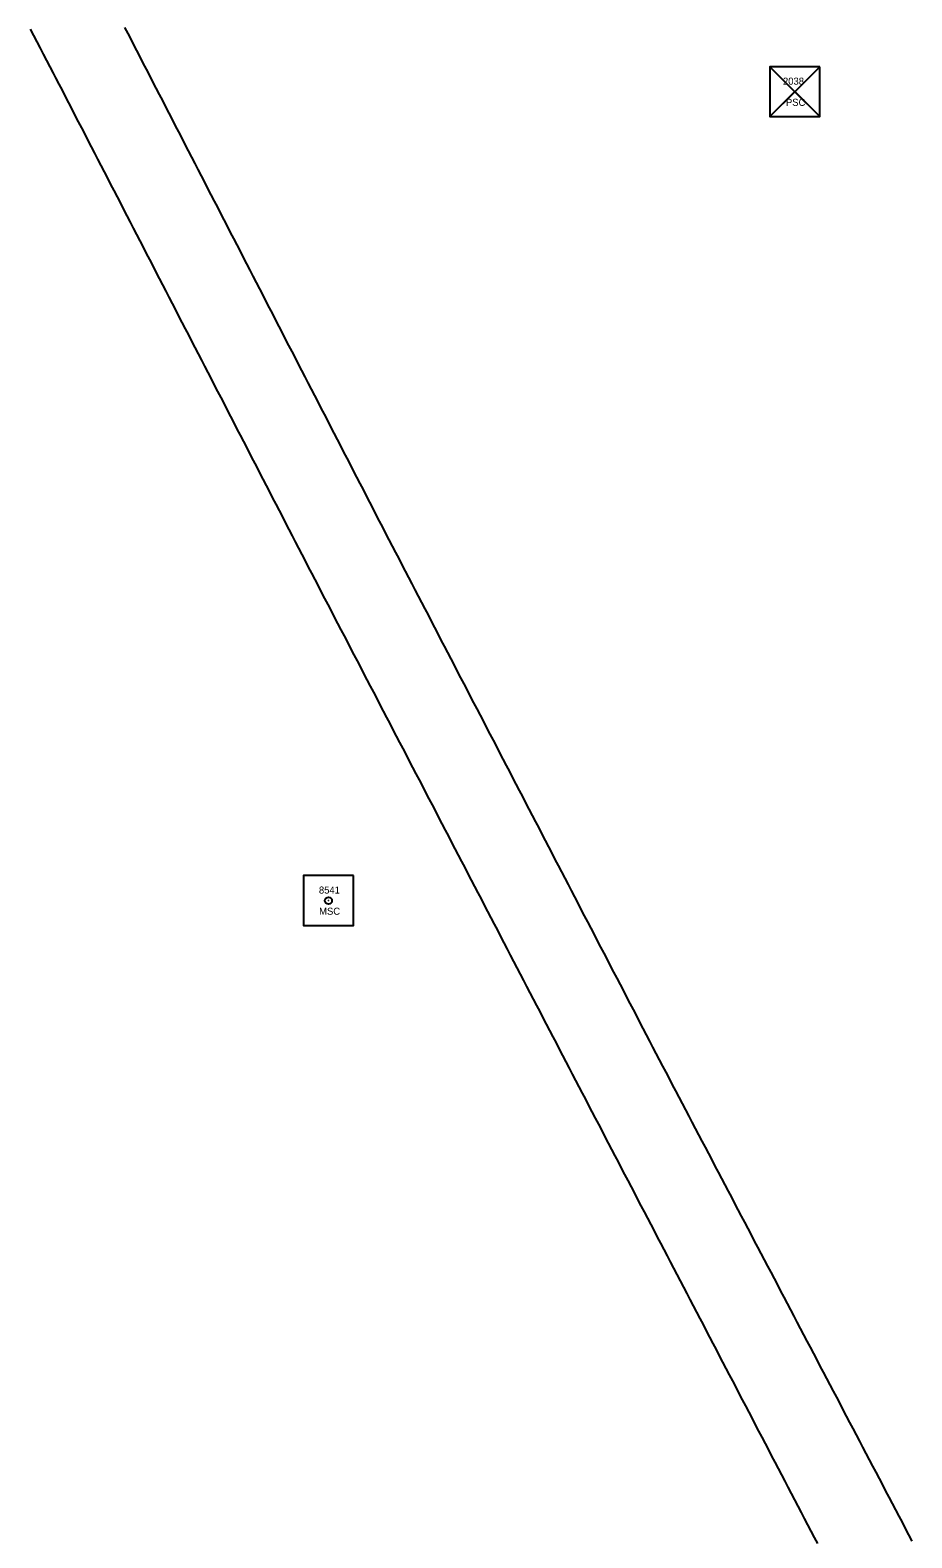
# Model space of a CAD drawing. Extents: x 205929 to 2357175, y -1785700 to 846739.
# Drawn here: x 2012224.1 to 2012349, y 825016.1 to 825229.6 of the extents above; entities that cross this region are included whole.
import ezdxf

# ---------------------------------------------------------------- set-up
doc = ezdxf.new("R2010")
doc.units = 0
for name, color, linetype in [('RD_HC_Survey', 7, 'Continuous'), ('RD_HC_txCode', 7, 'Continuous'), ('RD_Sketch1', 7, 'Continuous'), ('RD_SMD_Locator', 7, 'Continuous')]:
    doc.layers.add(name, color=color, linetype=linetype)

msp = doc.modelspace()

# ---------------------------------------------------------------- linework, layer by layer
at = {"layer": 'RD_HC_Survey'}
for p, q in [((2012328.86, 825224.42), (2012335.93, 825217.35)), ((2012335.93, 825224.42), (2012328.86, 825217.35)), ((2012335.93, 825224.42), (2012328.86, 825224.42)), ((2012328.86, 825224.42), (2012332.39, 825220.88)), ((2012332.39, 825220.88), (2012335.93, 825224.42)), ((2012332.39, 825220.88), (2012328.86, 825217.35)), ((2012335.93, 825217.35), (2012332.39, 825220.88)), ((2012328.86, 825217.35), (2012335.93, 825217.35))]:
    msp.add_line(p, q, dxfattribs=at)
for points in [[(2012335.93, 825224.42), (2012328.86, 825224.42), (2012328.86, 825217.35), (2012335.93, 825217.35)], [(2012269.87, 825109.85), (2012262.8, 825109.85), (2012262.8, 825102.78), (2012269.87, 825102.78)]]:
    msp.add_lwpolyline(points, close=True, dxfattribs=at)
msp.add_circle((2012266.34, 825106.31), 0.5, dxfattribs=at)
at = {"layer": 'RD_Sketch1'}
for points in [[(2012224.09, 825229.72), (2012224.56, 825228.84), (2012225.02, 825227.95), (2012225.49, 825227.07), (2012225.95, 825226.18), (2012226.41, 825225.29), (2012226.88, 825224.41), (2012227.34, 825223.52), (2012227.69, 825222.86), (2012228.15, 825221.97), (2012228.61, 825221.09), (2012229.07, 825220.2), (2012229.52, 825219.31), (2012229.98, 825218.42), (2012230.44, 825217.53), (2012230.9, 825216.64), (2012231.36, 825215.76), (2012231.82, 825214.87), (2012232.28, 825213.98), (2012232.74, 825213.09), (2012233.19, 825212.2), (2012233.65, 825211.31), (2012234.11, 825210.42), (2012234.57, 825209.54), (2012235.03, 825208.65), (2012235.49, 825207.76), (2012235.95, 825206.87), (2012236.41, 825205.98), (2012236.87, 825205.09), (2012237.32, 825204.2), (2012237.78, 825203.32), (2012238.24, 825202.43), (2012238.7, 825201.54), (2012239.16, 825200.65), (2012239.62, 825199.76), (2012240.08, 825198.87), (2012240.54, 825197.99), (2012240.99, 825197.1), (2012241.45, 825196.21), (2012241.91, 825195.32), (2012242.37, 825194.43), (2012242.83, 825193.54), (2012243.29, 825192.65), (2012243.75, 825191.77), (2012244.21, 825190.88), (2012244.67, 825189.99), (2012245.12, 825189.1), (2012245.58, 825188.21), (2012246.04, 825187.32), (2012246.5, 825186.43), (2012246.96, 825185.55), (2012247.42, 825184.66), (2012247.88, 825183.77), (2012248.34, 825182.88), (2012248.79, 825181.99), (2012249.25, 825181.1), (2012249.71, 825180.22), (2012250.17, 825179.33), (2012250.63, 825178.44), (2012251.09, 825177.55), (2012251.55, 825176.66), (2012252.01, 825175.77), (2012252.46, 825174.88), (2012252.92, 825174), (2012253.38, 825173.11), (2012253.84, 825172.22), (2012254.3, 825171.33), (2012254.76, 825170.44), (2012255.22, 825169.55), (2012255.68, 825168.66), (2012256.14, 825167.78), (2012256.59, 825166.89), (2012257.05, 825166), (2012257.51, 825165.11), (2012257.97, 825164.22), (2012258.43, 825163.33), (2012258.89, 825162.45), (2012259.35, 825161.56), (2012259.81, 825160.67), (2012260.26, 825159.78), (2012260.72, 825158.89), (2012261.18, 825158), (2012261.64, 825157.11), (2012262.1, 825156.23), (2012262.56, 825155.34), (2012263.02, 825154.45), (2012263.48, 825153.56), (2012263.94, 825152.67), (2012264.4, 825151.79), (2012264.86, 825150.9), (2012265.32, 825150.01), (2012265.78, 825149.12), (2012266.24, 825148.24), (2012266.71, 825147.35), (2012267.17, 825146.46), (2012267.63, 825145.58), (2012268.09, 825144.69), (2012268.55, 825143.8), (2012269.02, 825142.92), (2012269.48, 825142.03), (2012269.94, 825141.14), (2012270.4, 825140.26), (2012270.86, 825139.37), (2012271.32, 825138.48), (2012271.79, 825137.59), (2012272.25, 825136.71), (2012272.71, 825135.82), (2012273.17, 825134.93), (2012273.63, 825134.05), (2012274.09, 825133.16), (2012274.56, 825132.27), (2012275.02, 825131.39), (2012275.48, 825130.5), (2012275.94, 825129.61), (2012276.4, 825128.72), (2012276.87, 825127.84), (2012277.33, 825126.95), (2012277.79, 825126.06), (2012278.25, 825125.18), (2012278.71, 825124.29), (2012279.17, 825123.4), (2012279.64, 825122.52), (2012280.1, 825121.63), (2012280.56, 825120.74), (2012281.02, 825119.86), (2012281.48, 825118.97), (2012281.94, 825118.08), (2012282.41, 825117.19), (2012282.87, 825116.31), (2012283.33, 825115.42), (2012283.79, 825114.53), (2012284.25, 825113.65), (2012284.72, 825112.76), (2012285.18, 825111.87), (2012285.64, 825110.99), (2012286.1, 825110.1), (2012286.56, 825109.21), (2012287.02, 825108.33), (2012287.49, 825107.44), (2012287.95, 825106.55), (2012288.41, 825105.66), (2012288.87, 825104.78), (2012289.33, 825103.89), (2012289.8, 825103), (2012290.26, 825102.12), (2012290.72, 825101.23), (2012291.18, 825100.34), (2012291.64, 825099.46), (2012292.1, 825098.57), (2012292.57, 825097.68), (2012293.03, 825096.79), (2012293.49, 825095.91), (2012293.95, 825095.02), (2012294.41, 825094.13), (2012294.87, 825093.25), (2012295.34, 825092.36), (2012295.8, 825091.47), (2012296.26, 825090.59), (2012296.72, 825089.7), (2012297.18, 825088.81), (2012297.65, 825087.93), (2012298.11, 825087.04), (2012298.57, 825086.15), (2012299.03, 825085.26), (2012299.49, 825084.38), (2012299.95, 825083.49), (2012300.42, 825082.6), (2012300.88, 825081.72), (2012301.34, 825080.83), (2012301.8, 825079.94), (2012302.26, 825079.06), (2012302.73, 825078.17), (2012303.19, 825077.28), (2012303.65, 825076.4), (2012304.12, 825075.51), (2012304.58, 825074.63), (2012305.04, 825073.74), (2012305.5, 825072.85), (2012305.97, 825071.97), (2012306.43, 825071.08), (2012306.89, 825070.19), (2012307.36, 825069.31), (2012307.82, 825068.42), (2012308.28, 825067.53), (2012308.74, 825066.65), (2012309.21, 825065.76), (2012309.67, 825064.88), (2012310.13, 825063.99), (2012310.6, 825063.1), (2012311.06, 825062.22), (2012311.52, 825061.33), (2012311.98, 825060.44), (2012312.45, 825059.56), (2012312.91, 825058.67), (2012313.37, 825057.79), (2012313.84, 825056.9), (2012314.3, 825056.01), (2012314.76, 825055.13), (2012315.22, 825054.24), (2012315.69, 825053.35), (2012316.15, 825052.47), (2012316.61, 825051.58), (2012317.08, 825050.69), (2012317.54, 825049.81), (2012318, 825048.92), (2012318.46, 825048.04), (2012318.93, 825047.15), (2012319.39, 825046.26), (2012319.85, 825045.38), (2012320.32, 825044.49), (2012320.78, 825043.6), (2012321.24, 825042.72), (2012321.7, 825041.83), (2012322.17, 825040.94), (2012322.63, 825040.06), (2012323.09, 825039.17), (2012323.56, 825038.29), (2012324.02, 825037.4), (2012324.48, 825036.51), (2012324.94, 825035.63), (2012325.41, 825034.74), (2012325.87, 825033.85), (2012326.33, 825032.97), (2012326.8, 825032.08), (2012327.26, 825031.19), (2012327.72, 825030.31), (2012328.18, 825029.42), (2012328.65, 825028.54), (2012329.11, 825027.65), (2012329.57, 825026.76), (2012330.04, 825025.88), (2012330.5, 825024.99), (2012330.96, 825024.1), (2012331.42, 825023.22), (2012331.89, 825022.33), (2012332.35, 825021.45), (2012332.81, 825020.56), (2012333.28, 825019.67), (2012333.74, 825018.79), (2012334.2, 825017.9), (2012334.66, 825017.01), (2012335.13, 825016.13), (2012335.59, 825015.24)], [(2012237.44, 825229.99), (2012237.91, 825229.11), (2012238.38, 825228.22), (2012238.69, 825227.62), (2012239.15, 825226.73), (2012239.61, 825225.84), (2012240.07, 825224.95), (2012240.52, 825224.07), (2012240.98, 825223.18), (2012241.44, 825222.29), (2012241.9, 825221.4), (2012242.36, 825220.51), (2012242.82, 825219.62), (2012243.27, 825218.73), (2012243.73, 825217.84), (2012244.19, 825216.96), (2012244.65, 825216.07), (2012245.11, 825215.18), (2012245.57, 825214.29), (2012246.02, 825213.4), (2012246.48, 825212.51), (2012246.94, 825211.62), (2012247.4, 825210.73), (2012247.86, 825209.85), (2012248.32, 825208.96), (2012248.78, 825208.07), (2012249.23, 825207.18), (2012249.69, 825206.29), (2012250.15, 825205.4), (2012250.61, 825204.51), (2012251.07, 825203.63), (2012251.53, 825202.74), (2012251.98, 825201.85), (2012252.44, 825200.96), (2012252.9, 825200.07), (2012253.36, 825199.18), (2012253.82, 825198.29), (2012254.28, 825197.4), (2012254.73, 825196.52), (2012255.19, 825195.63), (2012255.65, 825194.74), (2012256.11, 825193.85), (2012256.57, 825192.96), (2012257.03, 825192.07), (2012257.48, 825191.18), (2012257.94, 825190.29), (2012258.4, 825189.41), (2012258.86, 825188.52), (2012259.32, 825187.63), (2012259.78, 825186.74), (2012260.23, 825185.85), (2012260.69, 825184.96), (2012261.15, 825184.07), (2012261.61, 825183.18), (2012262.07, 825182.3), (2012262.53, 825181.41), (2012262.99, 825180.52), (2012263.44, 825179.63), (2012263.9, 825178.74), (2012264.36, 825177.85), (2012264.82, 825176.96), (2012265.28, 825176.07), (2012265.74, 825175.19), (2012266.19, 825174.3), (2012266.65, 825173.41), (2012267.11, 825172.52), (2012267.57, 825171.63), (2012268.03, 825170.74), (2012268.49, 825169.85), (2012268.94, 825168.97), (2012269.4, 825168.08), (2012269.86, 825167.19), (2012270.32, 825166.3), (2012270.78, 825165.41), (2012271.24, 825164.52), (2012271.69, 825163.63), (2012272.15, 825162.74), (2012272.61, 825161.86), (2012273.07, 825160.97), (2012273.53, 825160.08), (2012273.99, 825159.19), (2012274.44, 825158.3), (2012274.9, 825157.41), (2012275.36, 825156.52), (2012275.83, 825155.64), (2012276.29, 825154.75), (2012276.75, 825153.86), (2012277.21, 825152.98), (2012277.67, 825152.09), (2012278.13, 825151.2), (2012278.59, 825150.31), (2012279.05, 825149.43), (2012279.52, 825148.54), (2012279.98, 825147.65), (2012280.44, 825146.77), (2012280.9, 825145.88), (2012281.36, 825144.99), (2012281.82, 825144.1), (2012282.28, 825143.22), (2012282.74, 825142.33), (2012283.2, 825141.44), (2012283.67, 825140.55), (2012284.13, 825139.67), (2012284.59, 825138.78), (2012285.05, 825137.89), (2012285.51, 825137.01), (2012285.97, 825136.12), (2012286.43, 825135.23), (2012286.89, 825134.34), (2012287.35, 825133.46), (2012287.82, 825132.57), (2012288.28, 825131.68), (2012288.74, 825130.79), (2012289.2, 825129.91), (2012289.66, 825129.02), (2012290.12, 825128.13), (2012290.58, 825127.25), (2012291.04, 825126.36), (2012291.5, 825125.47), (2012291.97, 825124.58), (2012292.43, 825123.7), (2012292.89, 825122.81), (2012293.35, 825121.92), (2012293.81, 825121.04), (2012294.27, 825120.15), (2012294.73, 825119.26), (2012295.19, 825118.37), (2012295.66, 825117.49), (2012296.12, 825116.6), (2012296.58, 825115.71), (2012297.04, 825114.82), (2012297.5, 825113.94), (2012297.96, 825113.05), (2012298.42, 825112.16), (2012298.88, 825111.28), (2012299.34, 825110.39), (2012299.81, 825109.5), (2012300.27, 825108.61), (2012300.73, 825107.73), (2012301.19, 825106.84), (2012301.65, 825105.95), (2012302.11, 825105.06), (2012302.57, 825104.18), (2012303.03, 825103.29), (2012303.49, 825102.4), (2012303.96, 825101.52), (2012304.42, 825100.63), (2012304.88, 825099.74), (2012305.34, 825098.85), (2012305.8, 825097.97), (2012306.26, 825097.08), (2012306.72, 825096.19), (2012307.18, 825095.31), (2012307.65, 825094.42), (2012308.11, 825093.53), (2012308.57, 825092.64), (2012309.03, 825091.76), (2012309.49, 825090.87), (2012309.95, 825089.98), (2012310.41, 825089.09), (2012310.87, 825088.21), (2012311.33, 825087.32), (2012311.8, 825086.43), (2012312.26, 825085.55), (2012312.72, 825084.66), (2012313.18, 825083.77), (2012313.65, 825082.89), (2012314.11, 825082), (2012314.58, 825081.12), (2012315.04, 825080.23), (2012315.51, 825079.35), (2012315.97, 825078.46), (2012316.43, 825077.57), (2012316.9, 825076.69), (2012317.36, 825075.8), (2012317.83, 825074.92), (2012318.29, 825074.03), (2012318.76, 825073.15), (2012319.22, 825072.26), (2012319.69, 825071.38), (2012320.15, 825070.49), (2012320.62, 825069.61), (2012321.08, 825068.72), (2012321.55, 825067.84), (2012322.01, 825066.95), (2012322.48, 825066.07), (2012322.94, 825065.18), (2012323.41, 825064.3), (2012323.87, 825063.41), (2012324.34, 825062.52), (2012324.8, 825061.64), (2012325.27, 825060.75), (2012325.73, 825059.87), (2012326.2, 825058.98), (2012326.66, 825058.1), (2012327.13, 825057.21), (2012327.59, 825056.33), (2012328.06, 825055.44), (2012328.52, 825054.56), (2012328.99, 825053.67), (2012329.45, 825052.79), (2012329.92, 825051.9), (2012330.38, 825051.02), (2012330.84, 825050.13), (2012331.31, 825049.24), (2012331.77, 825048.36), (2012332.24, 825047.47), (2012332.7, 825046.59), (2012333.17, 825045.7), (2012333.63, 825044.82), (2012334.1, 825043.93), (2012334.56, 825043.05), (2012335.03, 825042.16), (2012335.49, 825041.28), (2012335.96, 825040.39), (2012336.42, 825039.51), (2012336.89, 825038.62), (2012337.35, 825037.74), (2012337.82, 825036.85), (2012338.28, 825035.97), (2012338.75, 825035.08), (2012339.21, 825034.19), (2012339.68, 825033.31), (2012340.14, 825032.42), (2012340.61, 825031.54), (2012341.07, 825030.65), (2012341.54, 825029.77), (2012342, 825028.88), (2012342.47, 825028), (2012342.93, 825027.11), (2012343.4, 825026.23), (2012343.86, 825025.34), (2012344.32, 825024.46), (2012344.79, 825023.57), (2012345.25, 825022.69), (2012345.72, 825021.8), (2012346.18, 825020.91), (2012346.65, 825020.03), (2012347.11, 825019.14), (2012347.58, 825018.26), (2012348.04, 825017.37), (2012348.51, 825016.49), (2012348.97, 825015.6)]]:
    msp.add_lwpolyline(points, dxfattribs=at)
at = {"layer": 'RD_SMD_Locator'}
for centre in [(2012332.39, 825220.88), (2012266.34, 825106.31)]:
    msp.add_circle(centre, 0.001, dxfattribs=at)

# ---------------------------------------------------------------- texts
at = {"layer": 'RD_HC_txCode'}
for s, p in [('2038', (2012330.72, 825221.88)), ('PSC', (2012331.14, 825218.88)), ('8541', (2012264.99, 825107.31)), ('MSC', (2012265.02, 825104.31))]:
    msp.add_text(s, height=1, dxfattribs=at).set_placement(p)

doc.saveas('drawing.dxf')
